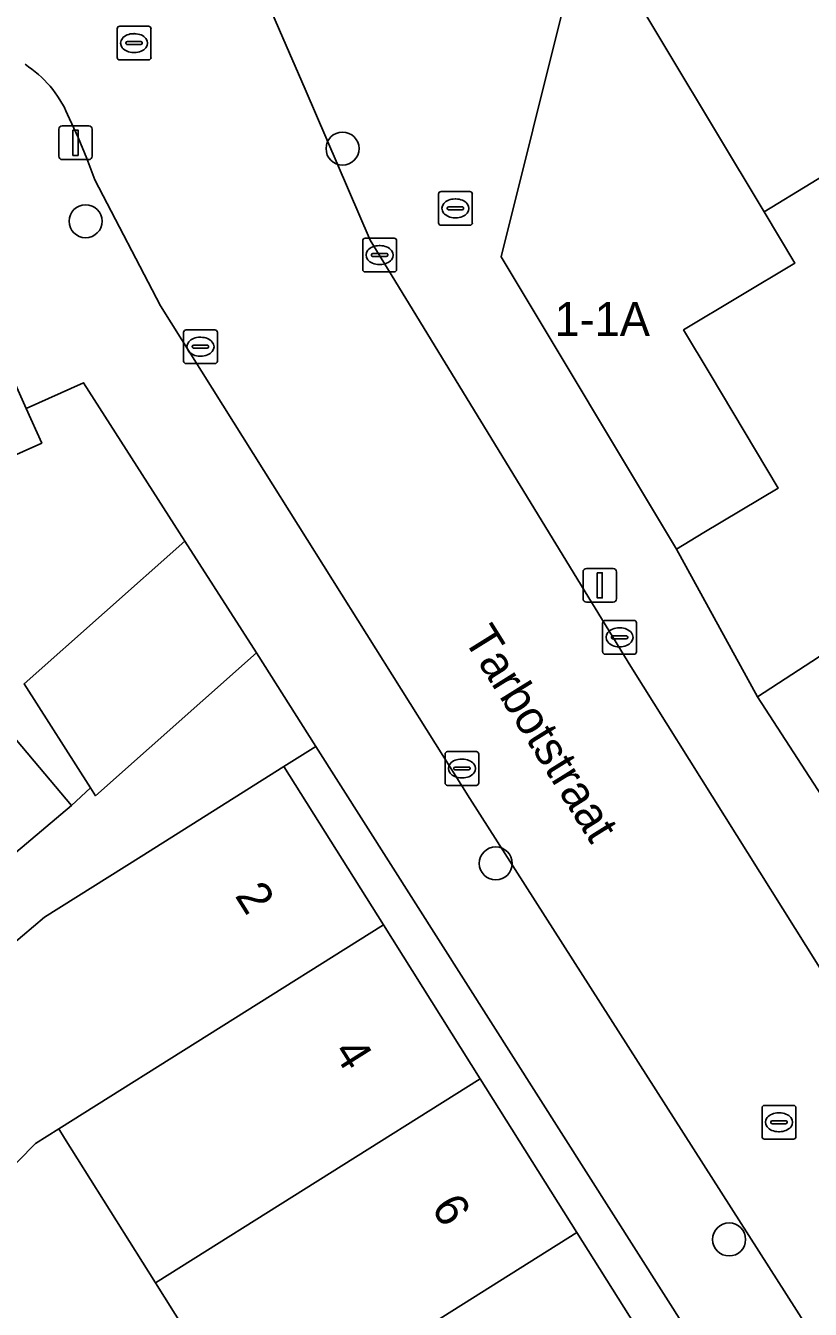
# Model space of a CAD drawing. Extents: x 159217 to 160349, y 381246 to 382172.
# Drawn here: x 159952.63 to 159975.89, y 381547.85 to 381585.9 of the extents above; entities that cross this region are included whole.
import ezdxf

# ---------------------------------------------------------------- set-up
doc = ezdxf.new("R2010")
doc.units = 0
for name, color, linetype in [('IMGEO_Boom', 7, 'Continuous'), ('IMGEO_Brandkraan', 7, 'Continuous'), ('IMGEO_Erf', 7, 'Continuous'), ('IMGEO_Kolk', 7, 'Continuous'), ('IMGEO_Lichtmast', 7, 'Continuous'), ('IMGEO_Muur', 7, 'Continuous'), ('IMGEO_Openbare_ruimte_label', 7, 'Continuous'), ('IMGEO_Pand', 7, 'Continuous'), ('IMGEO_Pand_nummerreeks', 7, 'Continuous'), ('IMGEO_Rijbaan_lokaal_open', 7, 'Continuous'), ('IMGEO_Rioolput', 7, 'Continuous'), ('IMGEO_Voetpad_open', 7, 'Continuous')]:
    doc.layers.add(name, color=color, linetype=linetype)

msp = doc.modelspace()

# ---------------------------------------------------------------- linework, layer by layer
at = {"layer": 'IMGEO_Boom'}
for centre in [(159962.022, 381582.259), (159954.41, 381580.104), (159966.562, 381561.072), (159973.48, 381549.925)]:
    msp.add_circle(centre, 0.489, dxfattribs=at)
at = {"layer": 'IMGEO_Brandkraan'}
for p, q in [((159964.943, 381580.988), (159965.795, 381580.988)), ((159964.868, 381580.062), (159964.868, 381580.914)), ((159965.356, 381580.768), (159965.381, 381580.768)), ((159965.869, 381580.914), (159965.869, 381580.062)), ((159965.127, 381580.482), (159965.127, 381580.494)), ((159965.565, 381580.445), (159965.167, 381580.445)), ((159965.17, 381580.531), (159965.568, 381580.531)), ((159965.379, 381580.208), (159965.354, 381580.208)), ((159965.611, 381580.494), (159965.611, 381580.482)), ((159965.795, 381579.988), (159964.943, 381579.988))]:
    msp.add_line(p, q, dxfattribs=at)
for points in [[(159964.943, 381580.988), (159965.795, 381580.988)], [(159964.868, 381580.062), (159964.868, 381580.914)], [(159965.869, 381580.914), (159965.869, 381580.062)], [(159965.795, 381579.988), (159964.943, 381579.988)]]:
    msp.add_lwpolyline(points, dxfattribs=at)
for centre, radius, start, end in [((159964.945, 381580.912), 0.0765, 91.552, 178.448), ((159964.945, 381580.912), 0.0765, 91.552, 178.448), ((159965.793, 381580.912), 0.0765, 1.552, 88.448), ((159965.793, 381580.912), 0.0765, 1.552, 88.448), ((159965.167, 381580.491), 0.0403, 85.8775, 175.7526), ((159965.164, 381580.481), 0.0366, 178.938, 274.7102), ((159965.568, 381580.488), 0.043, 264.8664, 352.4533), ((159965.572, 381580.493), 0.0386, 1.7309, 96.639), ((159964.945, 381580.064), 0.0765, 181.552, 268.448), ((159964.945, 381580.064), 0.0765, 181.552, 268.448), ((159965.793, 381580.064), 0.0765, 271.552, 358.448), ((159965.793, 381580.064), 0.0765, 271.552, 358.448)]:
    msp.add_arc(centre, radius, start, end, dxfattribs=at)
for centre, major_axis, ratio, start_param, end_param in [((159965.355, 381580.488), (-0.387, 0.002), 0.722429, 4.712389, 7.853982), ((159965.38, 381580.488), (-0.39, 0.002), 0.717154, 1.570796, 4.712389)]:
    msp.add_ellipse(centre, major_axis=major_axis, ratio=ratio, start_param=start_param, end_param=end_param, dxfattribs=at)
at = {"layer": 'IMGEO_Erf'}
for points in [[(159977.306, 381582.089), (159974.515, 381580.387), (159975.428, 381578.864), (159972.127, 381576.884), (159972.914, 381575.572), (159974.937, 381572.198), (159972.734, 381570.876), (159971.919, 381570.387), (159974.32, 381566.013), (159982.034, 381571.026), (159985.551, 381565.613), (159990.01, 381568.415), (159989.51, 381569.174), (159985.98, 381574.968), (159983.136, 381573.101)], [(159961.234, 381564.542), (159960.285, 381563.94), (159963.233, 381559.251), (159966.101, 381554.69), (159968.969, 381550.128), (159971.915, 381545.442), (159972.947, 381546.097)]]:
    msp.add_lwpolyline(points, close=True, dxfattribs=at)
for points in [[(159951.562, 381565.663), (159953.989, 381562.791), (159954.556, 381563.311), (159952.585, 381566.39), (159957.352, 381570.628), (159954.349, 381575.319), (159952.649, 381574.56), (159953.11, 381573.529), (159948.501, 381571.469)], [(159952.061, 381532.983), (159961.824, 381539.096), (159958.996, 381543.594), (159958.876, 381543.784), (159959.345, 381544.079), (159956.478, 381548.641), (159953.783, 381552.929), (159953.611, 381553.203), (159952.92, 381552.768), (159950.834, 381550.644)]]:
    msp.add_lwpolyline(points, dxfattribs=at)
at = {"layer": 'IMGEO_Kolk'}
for p, q in [((159962.622, 381578.678), (159962.622, 381579.53)), ((159962.697, 381579.604), (159963.549, 381579.604)), ((159963.623, 381579.53), (159963.623, 381578.678)), ((159962.881, 381579.098), (159962.881, 381579.11)), ((159962.924, 381579.147), (159963.322, 381579.147)), ((159963.11, 381579.384), (159963.135, 381579.384)), ((159963.365, 381579.11), (159963.365, 381579.098)), ((159963.319, 381579.061), (159962.921, 381579.061)), ((159963.133, 381578.824), (159963.108, 381578.824)), ((159963.549, 381578.604), (159962.697, 381578.604)), ((159957.312, 381575.962), (159957.312, 381576.814)), ((159957.387, 381576.888), (159958.239, 381576.888)), ((159958.313, 381576.814), (159958.313, 381575.962)), ((159957.614, 381576.431), (159958.012, 381576.431)), ((159957.8, 381576.668), (159957.825, 381576.668)), ((159957.571, 381576.382), (159957.571, 381576.394)), ((159958.009, 381576.345), (159957.611, 381576.345)), ((159957.823, 381576.108), (159957.798, 381576.108)), ((159958.055, 381576.394), (159958.055, 381576.382)), ((159958.239, 381575.888), (159957.387, 381575.888)), ((159969.731, 381567.347), (159969.731, 381568.199)), ((159969.806, 381568.273), (159970.658, 381568.273)), ((159970.219, 381568.053), (159970.244, 381568.053)), ((159970.732, 381568.199), (159970.732, 381567.347)), ((159969.99, 381567.767), (159969.99, 381567.779)), ((159970.428, 381567.73), (159970.03, 381567.73)), ((159970.033, 381567.816), (159970.431, 381567.816)), ((159970.474, 381567.779), (159970.474, 381567.767)), ((159970.658, 381567.273), (159969.806, 381567.273)), ((159970.242, 381567.493), (159970.217, 381567.493)), ((159965.061, 381563.46), (159965.061, 381564.312)), ((159965.136, 381564.386), (159965.988, 381564.386)), ((159966.062, 381564.312), (159966.062, 381563.46)), ((159965.32, 381563.88), (159965.32, 381563.892)), ((159965.363, 381563.929), (159965.761, 381563.929)), ((159965.549, 381564.166), (159965.574, 381564.166)), ((159965.804, 381563.892), (159965.804, 381563.88)), ((159965.758, 381563.843), (159965.36, 381563.843)), ((159965.572, 381563.606), (159965.547, 381563.606)), ((159965.988, 381563.386), (159965.136, 381563.386))]:
    msp.add_line(p, q, dxfattribs=at)
for points in [[(159962.622, 381578.678), (159962.622, 381579.53)], [(159962.697, 381579.604), (159963.549, 381579.604)], [(159963.623, 381579.53), (159963.623, 381578.678)], [(159963.549, 381578.604), (159962.697, 381578.604)], [(159957.312, 381575.962), (159957.312, 381576.814)], [(159957.387, 381576.888), (159958.239, 381576.888)], [(159958.313, 381576.814), (159958.313, 381575.962)], [(159958.239, 381575.888), (159957.387, 381575.888)], [(159969.731, 381567.347), (159969.731, 381568.199)], [(159969.806, 381568.273), (159970.658, 381568.273)], [(159970.732, 381568.199), (159970.732, 381567.347)], [(159970.658, 381567.273), (159969.806, 381567.273)], [(159965.061, 381563.46), (159965.061, 381564.312)], [(159965.136, 381564.386), (159965.988, 381564.386)], [(159966.062, 381564.312), (159966.062, 381563.46)], [(159965.988, 381563.386), (159965.136, 381563.386)]]:
    msp.add_lwpolyline(points, dxfattribs=at)
for centre, radius, start, end in [((159962.699, 381579.528), 0.0765, 91.552, 178.448), ((159962.699, 381579.528), 0.0765, 91.552, 178.448), ((159963.547, 381579.528), 0.0765, 1.552, 88.448), ((159963.547, 381579.528), 0.0765, 1.552, 88.448), ((159962.921, 381579.107), 0.0403, 85.8775, 175.7526), ((159962.918, 381579.097), 0.0366, 178.938, 274.7102), ((159963.322, 381579.104), 0.043, 264.8664, 352.4533), ((159963.326, 381579.109), 0.0386, 1.7309, 96.639), ((159962.699, 381578.68), 0.0765, 181.552, 268.448), ((159962.699, 381578.68), 0.0765, 181.552, 268.448), ((159963.547, 381578.68), 0.0765, 271.552, 358.448), ((159963.547, 381578.68), 0.0765, 271.552, 358.448), ((159957.389, 381576.812), 0.0765, 91.552, 178.448), ((159957.389, 381576.812), 0.0765, 91.552, 178.448), ((159958.237, 381576.812), 0.0765, 1.552, 88.448), ((159958.237, 381576.812), 0.0765, 1.552, 88.448), ((159957.611, 381576.391), 0.0403, 85.8775, 175.7526), ((159958.016, 381576.393), 0.0386, 1.7309, 96.639), ((159957.608, 381576.381), 0.0366, 178.938, 274.7102), ((159958.012, 381576.388), 0.043, 264.8664, 352.4533), ((159957.389, 381575.964), 0.0765, 181.552, 268.448), ((159957.389, 381575.964), 0.0765, 181.552, 268.448), ((159958.237, 381575.964), 0.0765, 271.552, 358.448), ((159958.237, 381575.964), 0.0765, 271.552, 358.448), ((159969.808, 381568.197), 0.0765, 91.552, 178.448), ((159969.808, 381568.197), 0.0765, 91.552, 178.448), ((159970.656, 381568.197), 0.0765, 1.552, 88.448), ((159970.656, 381568.197), 0.0765, 1.552, 88.448), ((159970.03, 381567.776), 0.0403, 85.8775, 175.7526), ((159970.027, 381567.766), 0.0366, 178.938, 274.7102), ((159970.431, 381567.773), 0.043, 264.8664, 352.4533), ((159970.435, 381567.778), 0.0386, 1.7309, 96.639), ((159969.808, 381567.349), 0.0765, 181.552, 268.448), ((159969.808, 381567.349), 0.0765, 181.552, 268.448), ((159970.656, 381567.349), 0.0765, 271.552, 358.448), ((159970.656, 381567.349), 0.0765, 271.552, 358.448), ((159965.138, 381564.31), 0.0765, 91.552, 178.448), ((159965.138, 381564.31), 0.0765, 91.552, 178.448), ((159965.986, 381564.31), 0.0765, 1.552, 88.448), ((159965.986, 381564.31), 0.0765, 1.552, 88.448), ((159965.36, 381563.889), 0.0403, 85.8775, 175.7526), ((159965.357, 381563.879), 0.0366, 178.938, 274.7102), ((159965.761, 381563.886), 0.043, 264.8664, 352.4533), ((159965.765, 381563.891), 0.0386, 1.7309, 96.639), ((159965.138, 381563.462), 0.0765, 181.552, 268.448), ((159965.138, 381563.462), 0.0765, 181.552, 268.448), ((159965.986, 381563.462), 0.0765, 271.552, 358.448), ((159965.986, 381563.462), 0.0765, 271.552, 358.448)]:
    msp.add_arc(centre, radius, start, end, dxfattribs=at)
for centre, major_axis, ratio, start_param, end_param in [((159963.109, 381579.104), (-0.387, 0.002), 0.722429, 4.712389, 7.853982), ((159963.134, 381579.104), (-0.39, 0.002), 0.717154, 1.570796, 4.712389), ((159957.799, 381576.388), (-0.387, 0.002), 0.722429, 4.712389, 7.853982), ((159957.824, 381576.388), (-0.39, 0.002), 0.717154, 1.570796, 4.712389), ((159970.218, 381567.773), (-0.387, 0.002), 0.722429, 4.712389, 7.853982), ((159970.243, 381567.773), (-0.39, 0.002), 0.717154, 1.570796, 4.712389), ((159965.548, 381563.886), (-0.387, 0.002), 0.722429, 4.712389, 7.853982), ((159965.573, 381563.886), (-0.39, 0.002), 0.717154, 1.570796, 4.712389)]:
    msp.add_ellipse(centre, major_axis=major_axis, ratio=ratio, start_param=start_param, end_param=end_param, dxfattribs=at)
at = {"layer": 'IMGEO_Lichtmast'}
for p, q in [((159953.714, 381582.932), (159954.504, 381582.932)), ((159954.504, 381582.932), (159953.714, 381582.932)), ((159953.614, 381582.032), (159953.614, 381582.832)), ((159953.614, 381582.832), (159953.614, 381582.032)), ((159954.604, 381582.832), (159954.604, 381582.032)), ((159954.604, 381582.032), (159954.604, 381582.832)), ((159954.504, 381581.932), (159953.714, 381581.932)), ((159953.714, 381581.932), (159954.504, 381581.932)), ((159969.149, 381568.914), (159969.149, 381569.714)), ((159969.149, 381569.714), (159969.149, 381568.914)), ((159969.249, 381569.814), (159970.039, 381569.814)), ((159970.039, 381569.814), (159969.249, 381569.814)), ((159970.139, 381569.714), (159970.139, 381568.914)), ((159970.139, 381568.914), (159970.139, 381569.714)), ((159970.039, 381568.814), (159969.249, 381568.814)), ((159969.249, 381568.814), (159970.039, 381568.814))]:
    msp.add_line(p, q, dxfattribs=at)
for points in [[(159954.034, 381582.807), (159954.184, 381582.807), (159954.184, 381582.057), (159954.034, 381582.057), (159954.034, 381582.807)], [(159969.569, 381569.689), (159969.719, 381569.689), (159969.719, 381568.939), (159969.569, 381568.939), (159969.569, 381569.689)]]:
    msp.add_lwpolyline(points, dxfattribs=at)
for centre, start, end in [((159953.714, 381582.832), 90, 180), ((159953.714, 381582.832), 90, 180), ((159954.504, 381582.832), 0, 90), ((159954.504, 381582.832), 360, 90), ((159953.714, 381582.032), 180, 270), ((159953.714, 381582.032), 180, 270), ((159954.504, 381582.032), 270, 0), ((159954.504, 381582.032), 270, 0), ((159969.249, 381569.714), 90, 180), ((159969.249, 381569.714), 90, 180), ((159970.039, 381569.714), 0, 90), ((159970.039, 381569.714), 360, 90), ((159969.249, 381568.914), 180, 270), ((159969.249, 381568.914), 180, 270), ((159970.039, 381568.914), 270, 0), ((159970.039, 381568.914), 270, 0)]:
    msp.add_arc(centre, 0.1, start, end, dxfattribs=at)
at = {"layer": 'IMGEO_Muur'}
msp.add_lwpolyline([(159952.649, 381574.56), (159954.349, 381575.319), (159957.352, 381570.628)], dxfattribs=at)
at = {"layer": 'IMGEO_Pand'}
for points in [[(159982.004, 381581.714), (159976.313, 381591.202), (159970.221, 381587.548), (159974.515, 381580.387), (159977.306, 381582.089), (159983.136, 381573.101), (159985.98, 381574.968), (159983.35, 381579.47)], [(159974.515, 381580.387), (159970.221, 381587.548), (159968.605, 381586.579), (159966.722, 381579.051), (159971.919, 381570.387), (159972.734, 381570.876), (159974.937, 381572.198), (159972.914, 381575.572), (159972.127, 381576.884), (159975.428, 381578.864)], [(159944.394, 381577.88), (159947.464, 381571.008), (159948.501, 381571.469), (159953.11, 381573.529), (159952.649, 381574.56), (159950.038, 381580.402)], [(159985.551, 381565.613), (159982.034, 381571.026), (159974.32, 381566.013), (159977.763, 381560.697)], [(159959.471, 381567.318), (159957.352, 381570.628), (159952.585, 381566.39), (159954.556, 381563.311), (159954.704, 381563.08)], [(159946.603, 381561.473), (159946.731, 381561.254), (159949.035, 381558.605), (159953.989, 381562.791), (159951.562, 381565.663)], [(159963.233, 381559.251), (159960.285, 381563.94), (159956.053, 381561.279), (159953.188, 381559.477), (159950.246, 381556.99), (159948.011, 381555.101), (159950.834, 381550.644), (159952.92, 381552.768), (159953.611, 381553.203)], [(159966.101, 381554.69), (159963.233, 381559.251), (159953.611, 381553.203), (159953.783, 381552.929), (159956.478, 381548.641)], [(159966.101, 381554.69), (159956.478, 381548.641), (159959.345, 381544.079), (159968.969, 381550.128)], [(159968.969, 381550.128), (159959.345, 381544.079), (159958.876, 381543.784), (159958.996, 381543.594), (159961.824, 381539.096), (159971.915, 381545.442)]]:
    msp.add_lwpolyline(points, close=True, dxfattribs=at)
at = {"layer": 'IMGEO_Rijbaan_lokaal_open'}
msp.add_lwpolyline([(159953.876, 381583.269), (159954.185, 381582.593), (159954.441, 381581.964), (159954.682, 381581.33), (159956.627, 381577.595), (159959.688, 381572.722), (159965.798, 381562.997), (159976.297, 381546.548), (159979.506, 381541.419), (159982.163, 381537.186), (159983.357, 381535.276), (159985.364, 381532.074), (159986.125, 381530.86), (159991.154, 381534.117), (159987.216, 381540.342), (159981.67, 381549.205), (159970.562, 381566.909), (159962.843, 381579.548), (159960.913, 381584.02), (159960.157, 381585.77), (159957.08, 381592.897)], dxfattribs=at)
msp.add_arc((159950.747, 381581.897), 3.417, 23.6782, 56.8359, dxfattribs=at)
at = {"layer": 'IMGEO_Rioolput'}
for p, q in [((159955.345, 381584.96), (159955.345, 381585.812)), ((159955.42, 381585.886), (159956.272, 381585.886)), ((159955.833, 381585.666), (159955.858, 381585.666)), ((159956.346, 381585.812), (159956.346, 381584.96)), ((159955.604, 381585.38), (159955.604, 381585.392)), ((159956.042, 381585.343), (159955.644, 381585.343)), ((159955.647, 381585.429), (159956.045, 381585.429)), ((159956.088, 381585.392), (159956.088, 381585.38)), ((159956.272, 381584.886), (159955.42, 381584.886)), ((159955.856, 381585.106), (159955.831, 381585.106)), ((159974.456, 381552.974), (159974.456, 381553.826)), ((159974.531, 381553.9), (159975.383, 381553.9)), ((159974.944, 381553.68), (159974.969, 381553.68)), ((159975.457, 381553.826), (159975.457, 381552.974)), ((159974.715, 381553.394), (159974.715, 381553.406)), ((159975.153, 381553.357), (159974.755, 381553.357)), ((159974.758, 381553.443), (159975.156, 381553.443)), ((159975.199, 381553.406), (159975.199, 381553.394)), ((159975.383, 381552.9), (159974.531, 381552.9)), ((159974.967, 381553.12), (159974.942, 381553.12))]:
    msp.add_line(p, q, dxfattribs=at)
for points in [[(159955.345, 381584.96), (159955.345, 381585.812)], [(159955.42, 381585.886), (159956.272, 381585.886)], [(159956.346, 381585.812), (159956.346, 381584.96)], [(159956.272, 381584.886), (159955.42, 381584.886)], [(159974.456, 381552.974), (159974.456, 381553.826)], [(159974.531, 381553.9), (159975.383, 381553.9)], [(159975.457, 381553.826), (159975.457, 381552.974)], [(159975.383, 381552.9), (159974.531, 381552.9)]]:
    msp.add_lwpolyline(points, dxfattribs=at)
for centre, radius, start, end in [((159955.422, 381585.81), 0.0765, 91.552, 178.448), ((159955.422, 381585.81), 0.0765, 91.552, 178.448), ((159956.27, 381585.81), 0.0765, 1.552, 88.448), ((159956.27, 381585.81), 0.0765, 1.552, 88.448), ((159955.644, 381585.389), 0.0403, 85.8775, 175.7526), ((159955.641, 381585.379), 0.0366, 178.938, 274.7102), ((159956.045, 381585.386), 0.043, 264.8664, 352.4533), ((159956.049, 381585.391), 0.0386, 1.7309, 96.639), ((159955.422, 381584.962), 0.0765, 181.552, 268.448), ((159955.422, 381584.962), 0.0765, 181.552, 268.448), ((159956.27, 381584.962), 0.0765, 271.552, 358.448), ((159956.27, 381584.962), 0.0765, 271.552, 358.448), ((159974.533, 381553.824), 0.0765, 91.552, 178.448), ((159974.533, 381553.824), 0.0765, 91.552, 178.448), ((159975.381, 381553.824), 0.0765, 1.552, 88.448), ((159975.381, 381553.824), 0.0765, 1.552, 88.448), ((159974.755, 381553.403), 0.0403, 85.8775, 175.7526), ((159974.752, 381553.393), 0.0366, 178.938, 274.7102), ((159975.156, 381553.4), 0.043, 264.8664, 352.4533), ((159975.16, 381553.405), 0.0386, 1.7309, 96.639), ((159974.533, 381552.976), 0.0765, 181.552, 268.448), ((159974.533, 381552.976), 0.0765, 181.552, 268.448), ((159975.381, 381552.976), 0.0765, 271.552, 358.448), ((159975.381, 381552.976), 0.0765, 271.552, 358.448)]:
    msp.add_arc(centre, radius, start, end, dxfattribs=at)
for centre, major_axis, ratio, start_param, end_param in [((159955.832, 381585.386), (-0.387, 0.002), 0.722429, 4.712389, 7.853982), ((159955.857, 381585.386), (-0.39, 0.002), 0.717154, 1.570796, 4.712389), ((159974.943, 381553.4), (-0.387, 0.002), 0.722429, 4.712389, 7.853982), ((159974.968, 381553.4), (-0.39, 0.002), 0.717154, 1.570796, 4.712389)]:
    msp.add_ellipse(centre, major_axis=major_axis, ratio=ratio, start_param=start_param, end_param=end_param, dxfattribs=at)
at = {"layer": 'IMGEO_Voetpad_open'}
for points in [[(159957.08, 381592.897), (159960.157, 381585.77), (159960.913, 381584.02), (159962.843, 381579.548), (159970.562, 381566.909), (159981.67, 381549.205), (159987.216, 381540.342)], [(159996.445, 381531.405), (159981.154, 381555.607), (159980.681, 381555.294), (159977.514, 381560.547), (159977.763, 381560.697), (159974.32, 381566.013), (159971.919, 381570.387), (159966.722, 381579.051), (159968.605, 381586.579)], [(159948.019, 381585.239), (159949.504, 381581.701), (159950.038, 381580.402), (159952.649, 381574.56), (159954.349, 381575.319), (159957.352, 381570.628), (159959.471, 381567.318), (159961.234, 381564.542), (159972.947, 381546.097), (159973.736, 381544.855), (159975.35, 381542.289), (159976.968, 381539.715), (159980.016, 381534.943), (159983.501, 381529.306), (159985.588, 381526.009), (159985.706, 381525.704)], [(159965.798, 381562.997), (159959.688, 381572.722), (159956.627, 381577.595), (159954.682, 381581.33), (159954.441, 381581.964), (159954.185, 381582.593), (159953.876, 381583.269)], [(159950.246, 381556.99), (159953.188, 381559.477), (159956.053, 381561.279), (159960.285, 381563.94), (159961.234, 381564.542), (159959.471, 381567.318), (159954.704, 381563.08), (159954.556, 381563.311), (159953.989, 381562.791), (159949.035, 381558.605)], [(159987.328, 381528.952), (159986.549, 381530.183), (159986.125, 381530.86), (159985.364, 381532.074), (159983.357, 381535.276), (159982.163, 381537.186), (159979.506, 381541.419), (159976.297, 381546.548), (159965.798, 381562.997)]]:
    msp.add_lwpolyline(points, dxfattribs=at)
msp.add_arc((159950.747, 381581.897), 3.417, 23.6782, 56.8359, dxfattribs=at)

# ---------------------------------------------------------------- texts
at = {"layer": 'IMGEO_Openbare_ruimte_label'}
msp.add_text('Tarbotstraat', height=1, rotation=301.9265, dxfattribs=at).set_placement((159965.589, 381567.734))
at = {"layer": 'IMGEO_Pand_nummerreeks'}
msp.add_text('1-1A', height=1, dxfattribs=at).set_placement((159968.307, 381576.709))
for s, rotation, p in [('2', 302.1599, (159958.815, 381560.117)), ('4', 302.1583, (159961.723, 381555.491)), ('6', 302.1583, (159964.631, 381550.866))]:
    msp.add_text(s, height=1, rotation=rotation, dxfattribs=at).set_placement(p)

doc.saveas('drawing.dxf')
